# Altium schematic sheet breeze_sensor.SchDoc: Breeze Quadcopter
size A4; Author: myyerrol; Organization: Team MicroDynamics; Address1: NWPU; Address2: Xi'an; Address3: Shannxi; Address4: China; Revision: V0.1; SheetNumber: 4; SheetTotal: 5
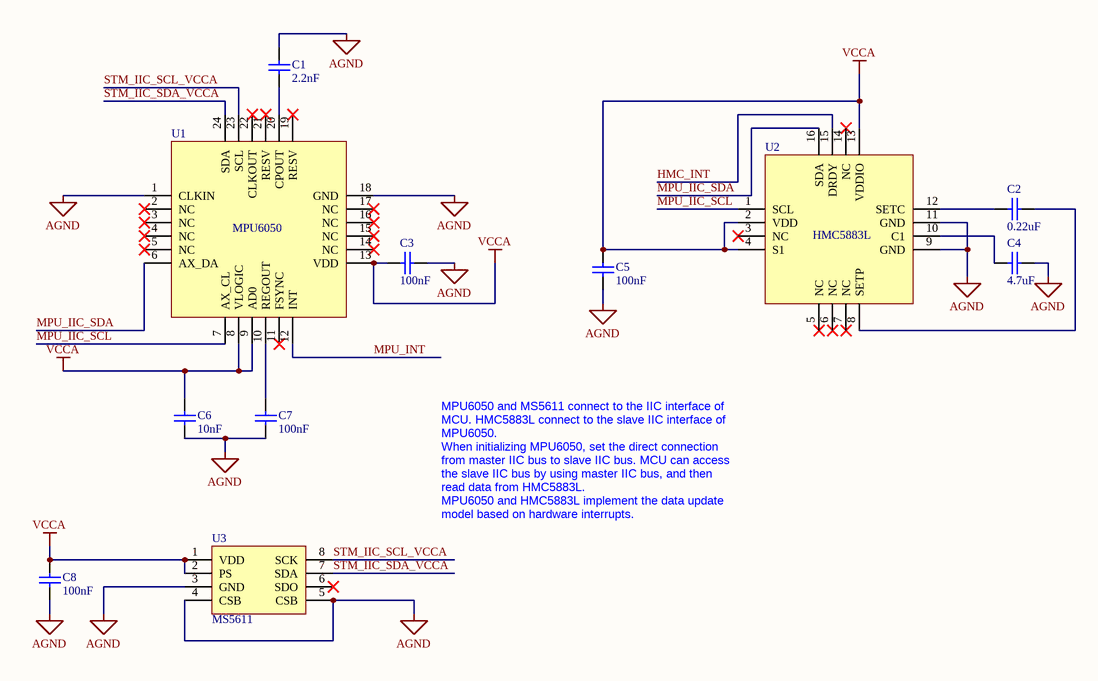
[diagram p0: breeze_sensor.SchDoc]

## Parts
C1  value 2.2nF  [SMD-0603]  (hidden comment: CAP-0603)
C2  value 0.22uF  [SMD-0603]  (hidden comment: CAP-0603)
C3  value 100nF  [SMD-0603]  (hidden comment: CAP-0603)
C4  value 4.7uF  [SMD-0603]  (hidden comment: CAP-0603)
C5  value 100nF  [SMD-0603]  (hidden comment: CAP-0603)
C6  value 10nF  [SMD-0603]  (hidden comment: CAP-0603)
C7  value 100nF  [SMD-0603]  (hidden comment: CAP-0603)
C8  value 100nF  [SMD-0603]  (hidden comment: CAP-0603)
U1  MPU6050  [QFN-24]
U2  HMC5883L  [LPCC-16]
U3  MS5611  [MS5611]

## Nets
AGND: C1.2 C3.2 C4.2 C5.2 C6.2 C7.2 C8.2 U1.1(CLKIN) U1.18(GND) U2.9(GND) U2.11(GND) U3.3(GND) U3.4(CSB) U3.5(CSB)
VCCA: C3.1 C5.1 C6.1 C8.1 U1.8(VLOGIC) U1.9(AD0) U1.13(VDD) U2.2(VDD) U2.4(S1) U2.13(VDDIO) U3.1(VDD) U3.2(PS)
HMC_INT: U2.15(DRDY)
MPU_IIC_SCL: U1.7(AX_CL) U2.1(SCL)
MPU_IIC_SDA: U1.6(AX_DA) U2.16(SDA)
MPU_INT: U1.12(INT)
STM_IIC_SCL_VCCA: U1.23(SCL) U3.8(SCK)
STM_IIC_SDA_VCCA: U1.24(SDA) U3.7(SDA)
NetC1_1: C1.1 U1.20(CPOUT)
NetC2_1: C2.1 U2.12(SETC)
NetC2_2: C2.2 U2.8(SETP)
NetC4_1: C4.1 U2.10(C1)
NetC7_1: C7.1 U1.10(REGOUT)

Not connected (* = marked no-connect by the designer): U1 2(NC)* 3(NC)* 4(NC)* 5(NC)* 11(FSYNC)* 14(NC)* 15(NC)* 16(NC)* 17(NC)* 19(RESV)* 21(RESV)* 22(CLKOUT)*; U2 3(NC)* 5(NC)* 6(NC)* 7(NC)* 14(NC)*; U3 6(SDO)*

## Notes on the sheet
- MPU6050 and MS5611 connect to the IIC interface of MCU. HMC5883L connect to the slave IIC interface of MPU6050.
  When initializing MPU6050, set the direct connection from master IIC bus to slave IIC bus. MCU can access the slave IIC bus by using master IIC bus, and then read data from HMC5883L.
  MPU6050 and HMC5883L implement the data update model based on hardware interrupts.

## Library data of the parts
C1-C8 = CAP-0603: Capacitor
U1 = MPU6050: 6-axis Motion Tracking IC
U2 = HMC5883L: 3-Axis Digital Compass IC
U3 = MS5611: High Resolution Altimeter IC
